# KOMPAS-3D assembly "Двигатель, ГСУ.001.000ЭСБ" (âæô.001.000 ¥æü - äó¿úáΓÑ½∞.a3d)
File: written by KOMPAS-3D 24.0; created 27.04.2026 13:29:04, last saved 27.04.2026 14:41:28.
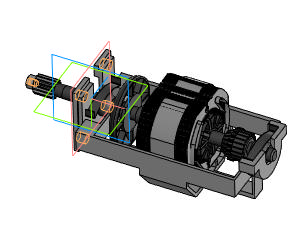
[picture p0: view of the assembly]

Document properties: Автор: USG_411; Полное имя файла: ГСУ.001.000 СБ - Двигатель Сборочный чертеж.cdw

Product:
- Component [detail]: Рама двигателя  | designation ГСУ.001.001  | qty 1  | pos. 2  | Масса: 0.2349; Автор: USG_411; source file: ГСУ.001.001 ЭСБ - Рама двигателя.m3d
- Component [assembly]: Ротор  | designation ГСУ.001.100  | qty 1  | pos. 1  | Масса: 0.24841; Автор: USG_411; source file: ГСУ.001.100 ЭСБ - Ротор.a3d
- Component [detail]: Пластина  | designation ГСУ.001.005  | qty 2  | pos. 4  | Масса: 0.002575; Автор: USG_411; source file: ГСУ.001.005 ЭМД - Пластина.m3d
- Component [detail]: Основание статора  | designation ГСУ.001.002  | qty 1  | pos. 3  | Масса: 0.249145; Автор: USG_411; source file: ГСУ.001.002 ЭМД - Основание статора.m3d
- Component [detail]: Пластина держателя втулок  | designation ГСУ.001.013  | qty 2  | pos. 5  | Масса: 0.000654; Автор: USG_411; source file: ГСУ.001.013 ЭМД - Пластина держателя втулок.m3d
- Component [detail]: Держатель статора  | designation ГСУ.001.012  | qty 1  | Масса: 0.003633; Автор: USG_411; source file: ГСУ.001.012 ЭМД - Держатель статора.m3d
- Part/product: Двигатель  | designation ГСУ.001.000ЭСБ
    Масса: 0.738912
    Форматы листов документа: A4
    source file: ГСУ.001.000 - Двигатель СП.spw

Referenced files in C:\Users\USG_411.STUD\Desktop\ГМ2704_411-23\Двигатель мясорубки\: ГСУ.001.001 ЭСБ - Рама двигателя.m3d, ГСУ.001.100 ЭСБ - Ротор.a3d, ГСУ.001.005 ЭМД - Пластина.m3d, ГСУ.001.002 ЭМД - Основание статора.m3d, ГСУ.001.013 ЭМД - Пластина держателя втулок.m3d, ГСУ.001.012 ЭМД - Держатель статора.m3d
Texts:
  ГСУ.001.000
  ГСУ.001.000 ЭСБ
  ГСУ.001.001 Рама двигателя
  ГСУ.001.100 Ротор
  ГСУ.001.005 Пластина (1)
  ГСУ.001.005 Пластина (2)
  ГСУ.001.002 Основание статора
  ГСУ.001.013 Пластина держателя втулок (1)
  ГСУ.001.013 Пластина держателя втулок (2)
  ГСУ.001.012 Держатель статора
  Грань.Элемент выдавливания:2.Экземпляр ( 1, 4 )
  Грань.Тело 1.Экземпляр ( 2 )
  Грань.Тело 1.Экземпляр ( 46, 1 )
